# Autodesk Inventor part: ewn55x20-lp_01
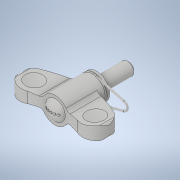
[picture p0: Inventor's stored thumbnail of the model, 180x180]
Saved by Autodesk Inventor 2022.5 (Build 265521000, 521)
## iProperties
Created: 2021-08
Part Number: ewn55x20-lp_01
Material: 一般
Document SubType Name: Modeling
Designer: ImaoCorp
Density: 1 g/cm^3
Appearance: 既定
Author: ImaoCorp
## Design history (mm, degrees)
feature "ewn55x20-lp_01"
node "ソリッド1"
